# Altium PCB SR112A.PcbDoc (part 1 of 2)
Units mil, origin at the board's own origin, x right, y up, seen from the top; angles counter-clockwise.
Board outline 4000 x 3000 mil, 4 copper layers (Top Layer, Signal Layer 1, Signal Layer 2, Bottom Layer), stack 61.2 mil thick; 97 components, 25 nets, 179 pads, 677 vias.
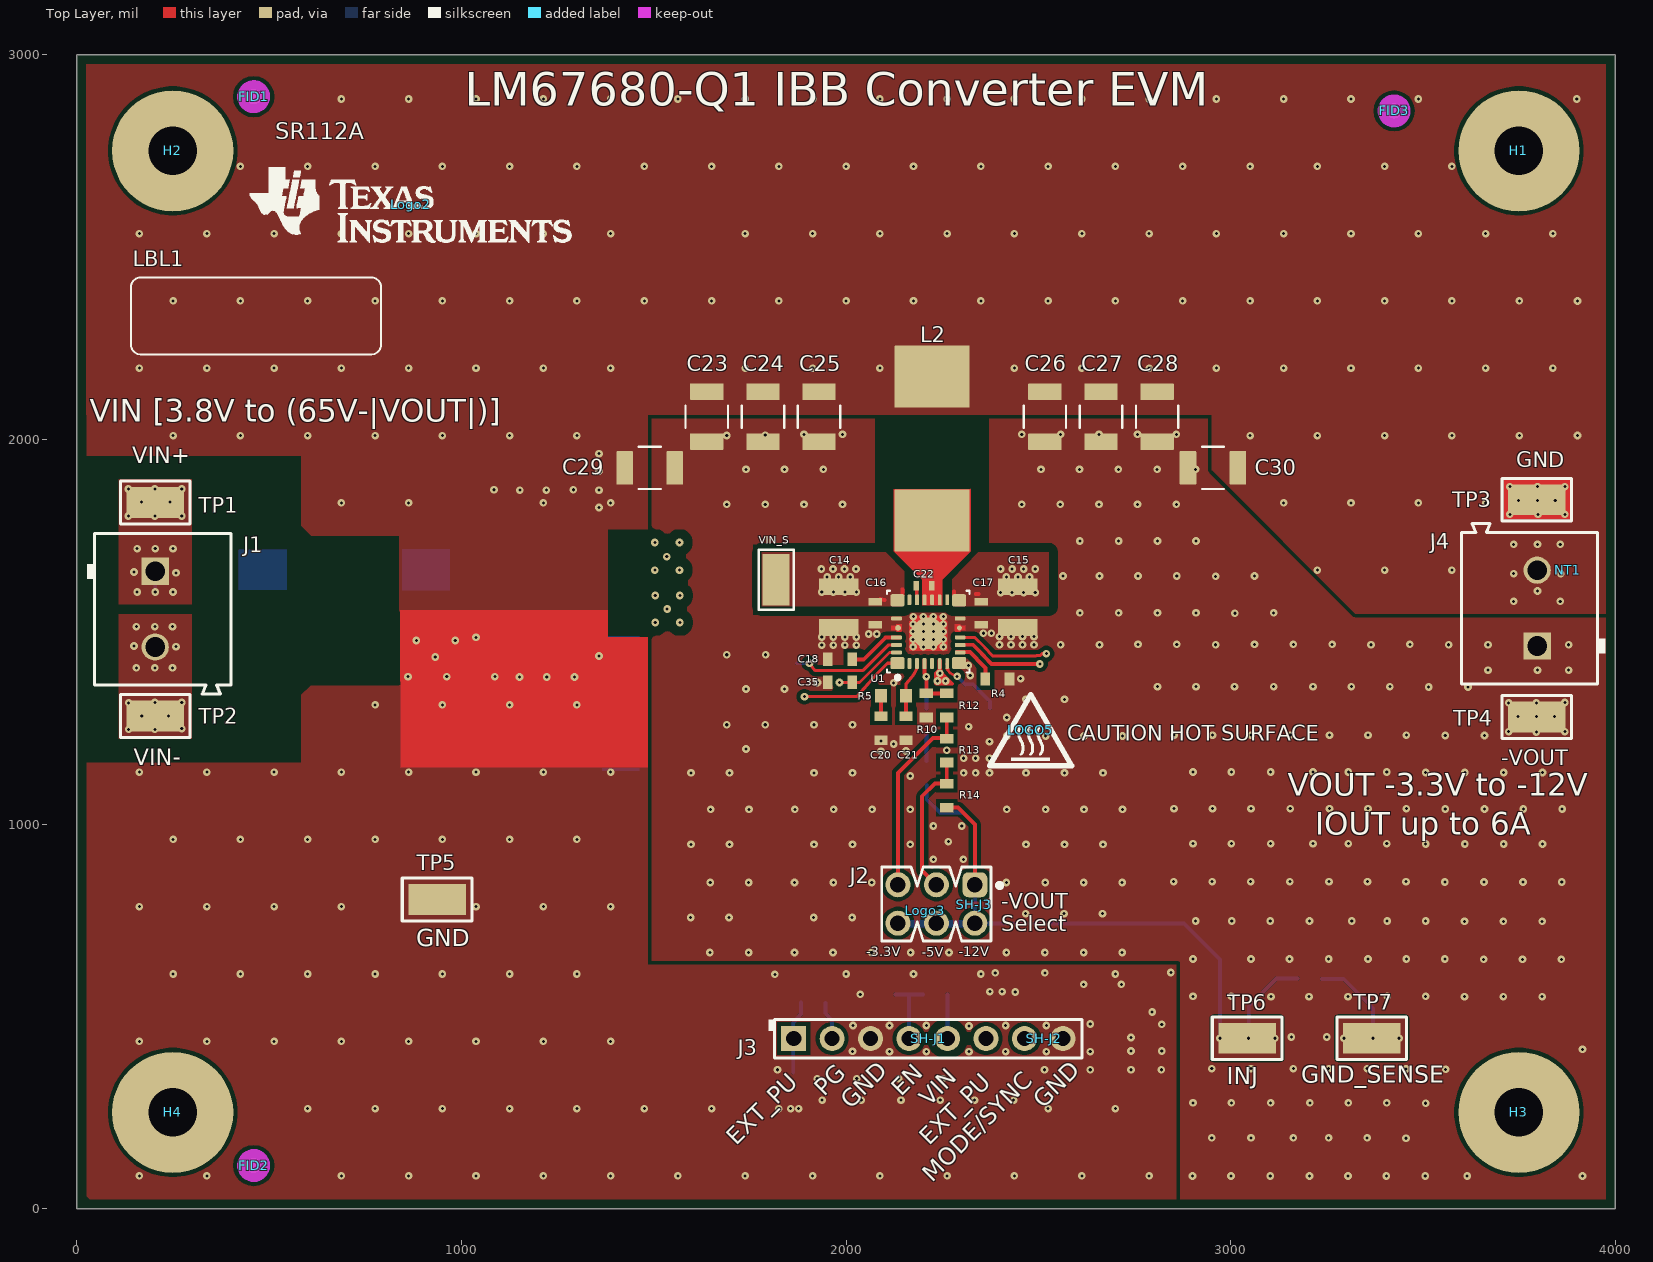
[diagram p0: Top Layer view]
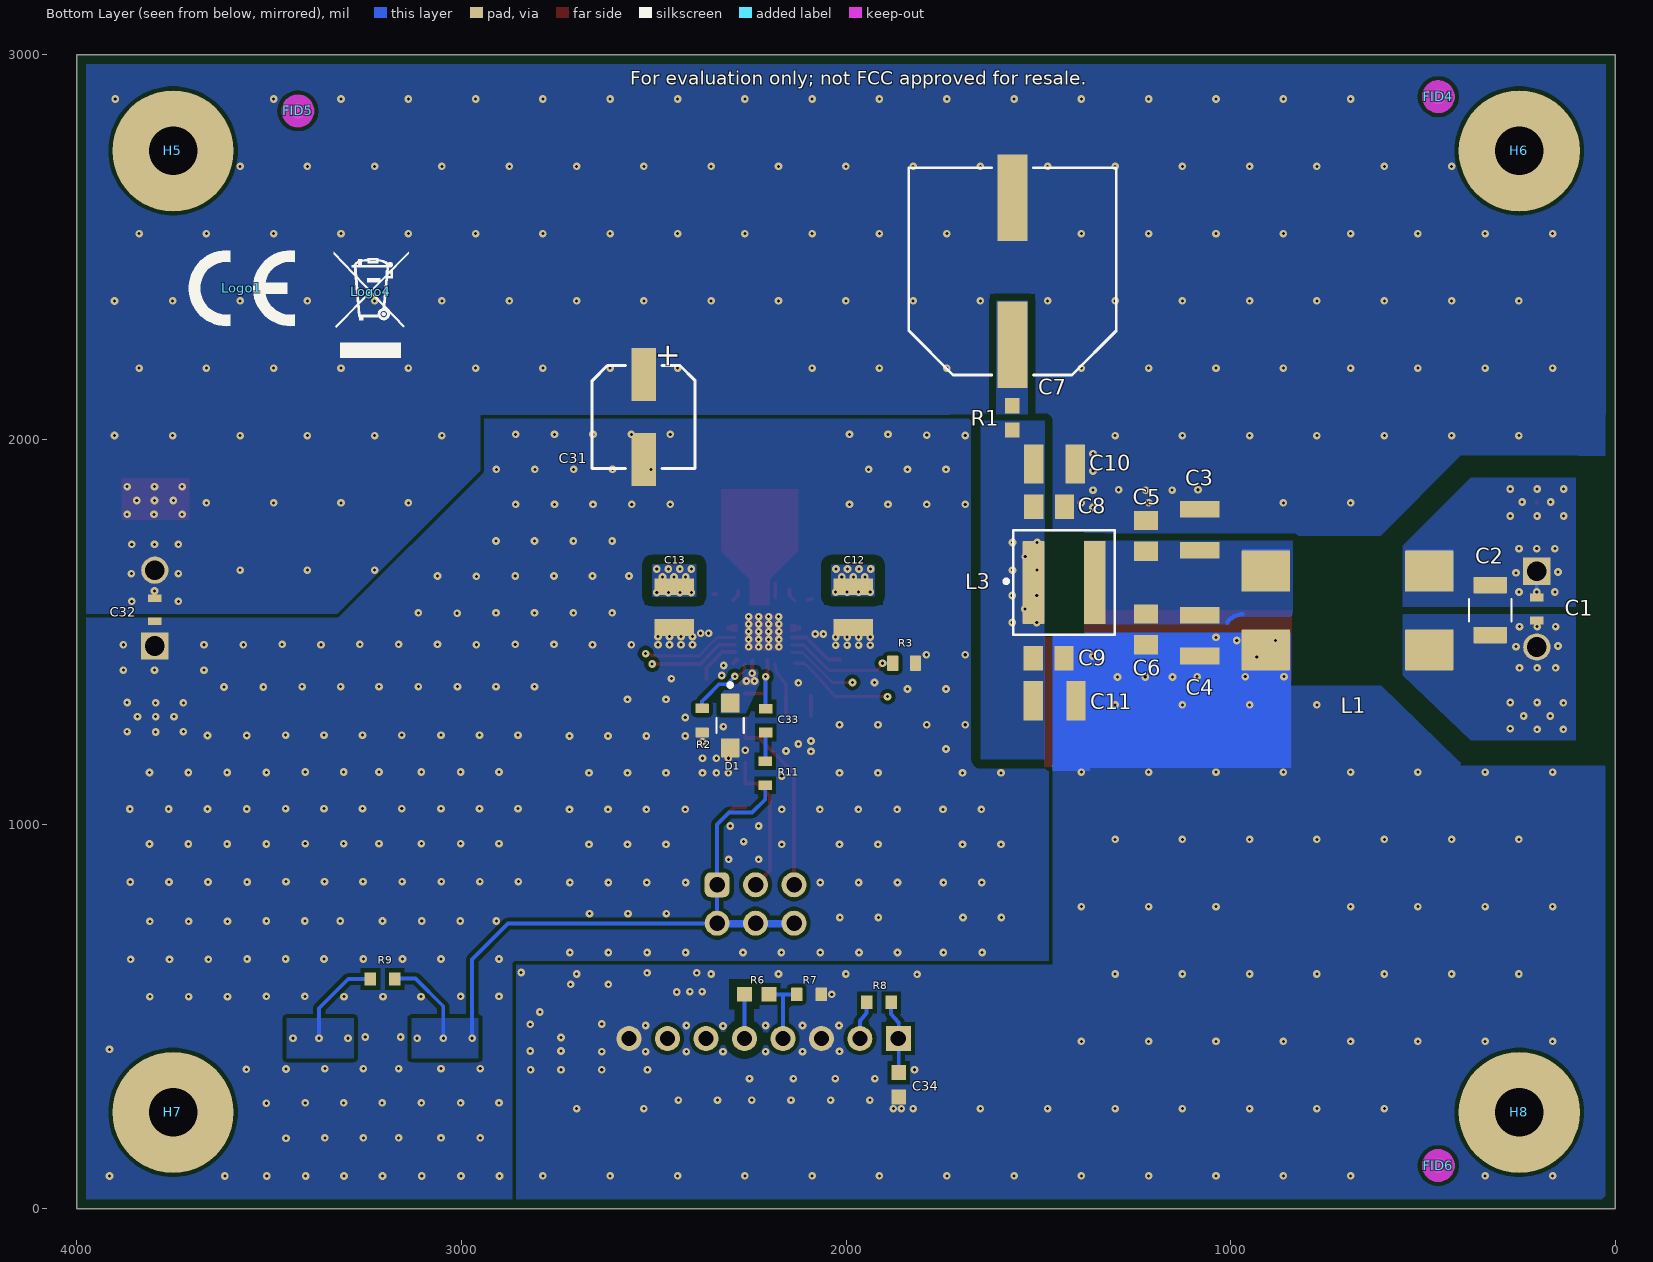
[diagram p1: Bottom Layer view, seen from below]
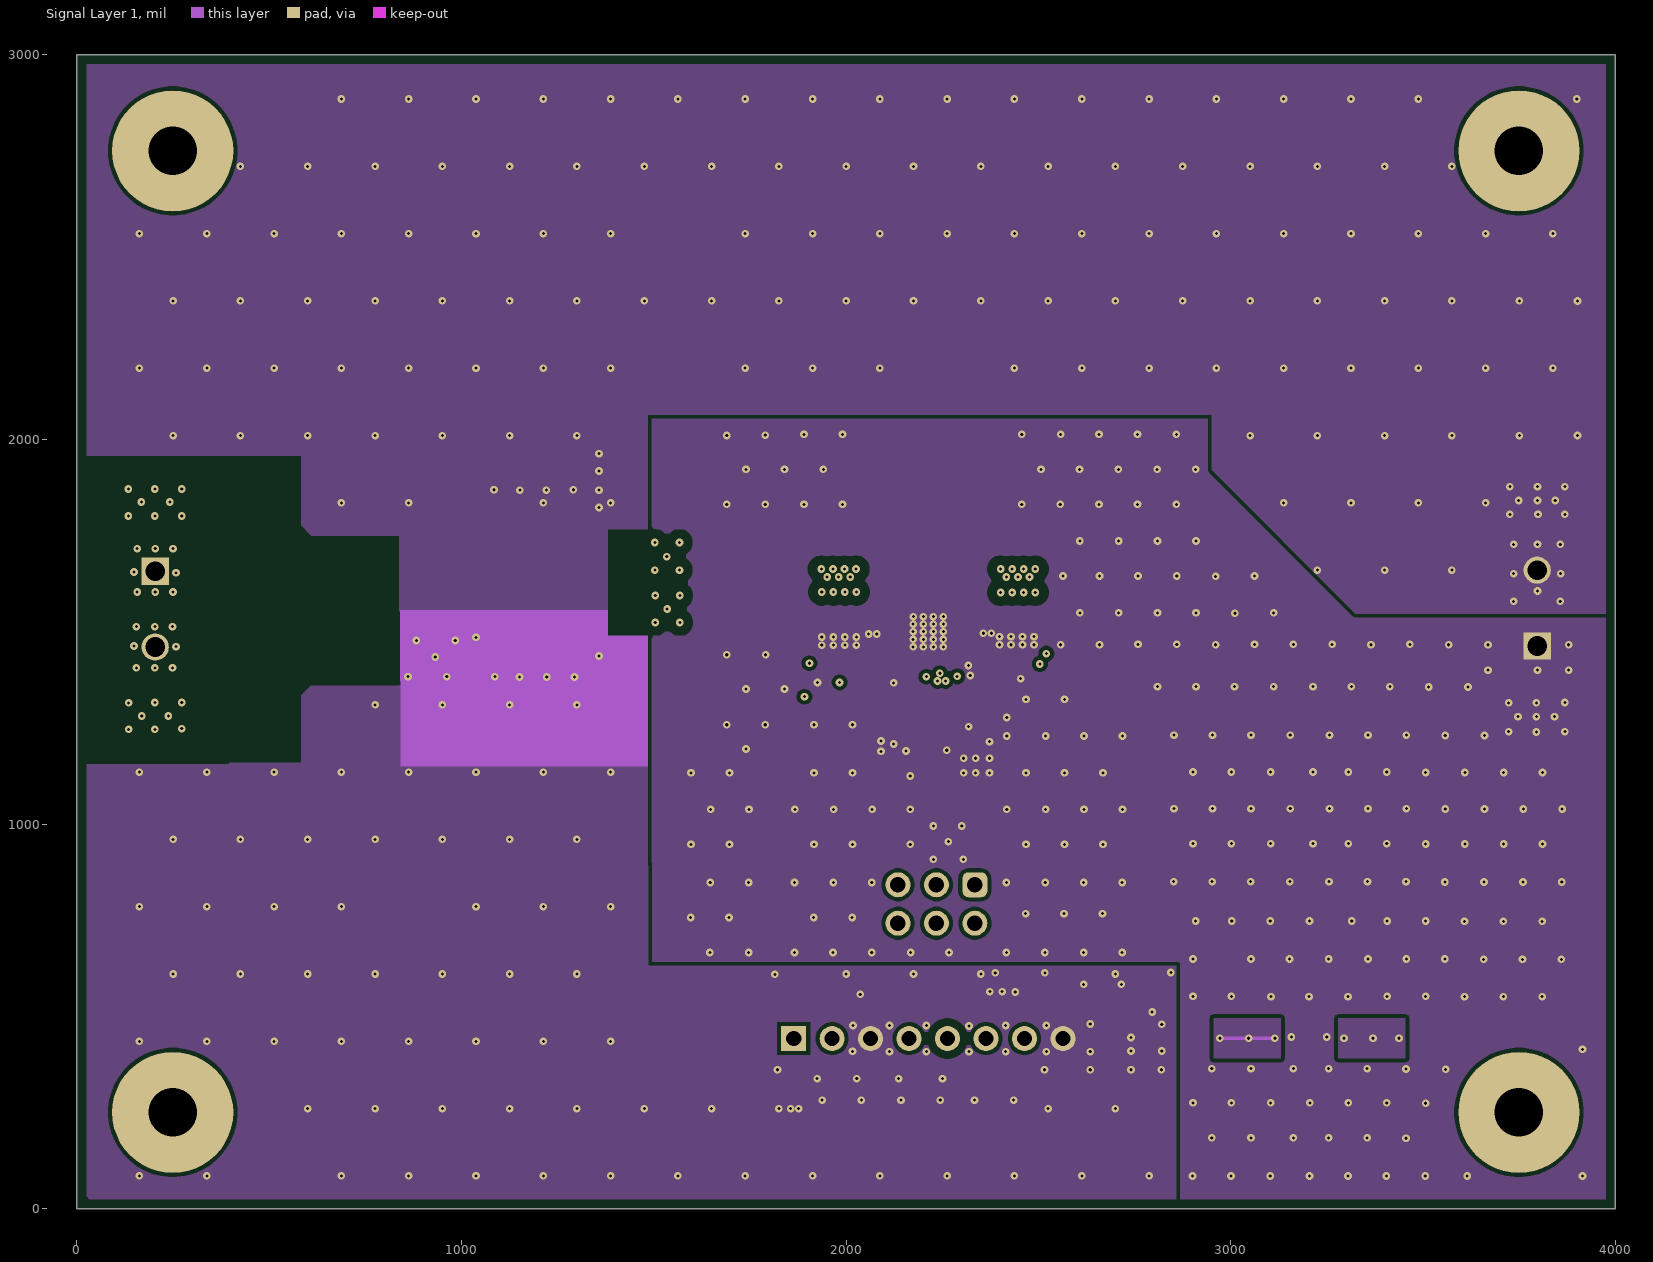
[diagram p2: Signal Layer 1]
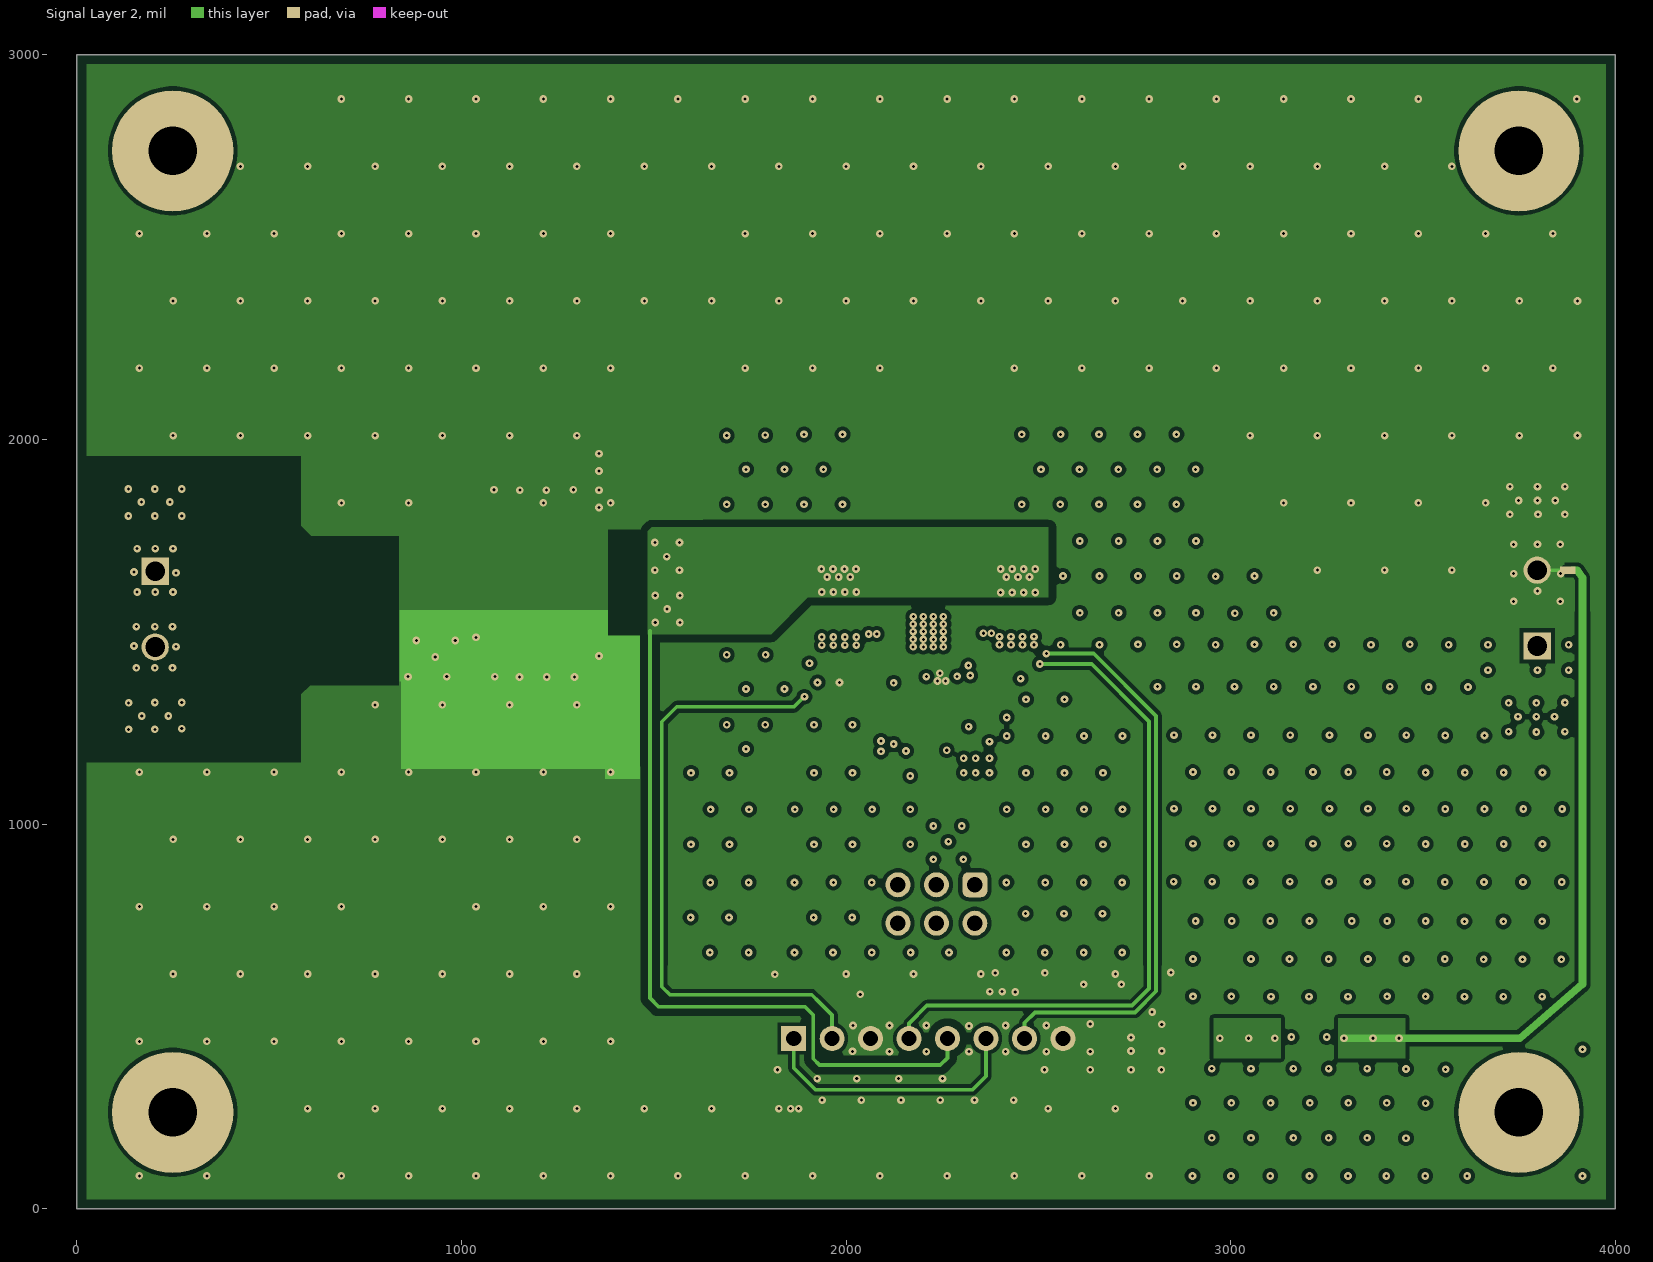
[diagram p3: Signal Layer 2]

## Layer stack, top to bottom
Top Solder: solder mask 0.4, Solder Resist, Dk 3.5
Top Layer: signal copper 2.8
Dielectric1: core 5, FR-4 High Tg, Dk 4.2
Signal Layer 1: signal copper 2.8
Dielectric 2: prepreg 40, FR-4 High Tg, Dk 4.2
Signal Layer 2: signal copper 2.8
Dielectric 3: core 5, FR-4 High Tg, Dk 4.2
Bottom Layer: signal copper 2.8
Bottom Solder: solder mask 0.4, Solder Resist, Dk 3.5

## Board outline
0,0 4000,0 4000,3000 0,3000

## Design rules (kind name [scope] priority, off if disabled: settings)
AcuteAngle [All] p1: minimum=4.50000000000000E+0001 checktracksonly=FALSE
AssemblyTestPointUsage [All] p1: valid=2
BoardOutlineClearance BoardOutlineClearance_MountingHoles [OnCopper and InComponentClass('Mounting Holes')] p1: gap=40 ignorepadtopadclearanceinfootprint=FALSE
BoardOutlineClearance BoardOutlineClearance_Poly [OnCopper and IsPoly] p2: gap=25 ignorepadtopadclearanceinfootprint=FALSE
BoardOutlineClearance [OnCopper and Not InComponentClass('Logo') and not InComponentClass('FiducialMark') and not InRegion(1000,500,4000,800) and not InPoly] p3: gap=75 ignorepadtopadclearanceinfootprint=FALSE
Clearance Clearance_2 [InNet('VIN') vs InNet('-VOUT')] p1: gap=25 ignorepadtopadclearanceinfootprint=TRUE
Clearance "NetC7_1 to GND" [InNet('NetC7_1') vs InNet('GND')] p2: gap=20 ignorepadtopadclearanceinfootprint=FALSE
Clearance "NetC3_1 to GND" [InNet('NetC3_1') vs InNet('GND')] p3: gap=20 ignorepadtopadclearanceinfootprint=FALSE
Clearance "VIN+ to GND" [InNet('VIN+') vs InNet('GND')] p4: gap=20 ignorepadtopadclearanceinfootprint=FALSE
Clearance "VIN- to GND" [InNet('VIN-') vs InNet('GND')] p5: gap=20 ignorepadtopadclearanceinfootprint=FALSE
Clearance "VIN+ to VIN-" [InNet('VIN+') vs InNet('VIN-')] p6: gap=20 ignorepadtopadclearanceinfootprint=FALSE
Clearance "Vin to GND" [InNet('VIN') vs InNet('GND')] p7: gap=20 ignorepadtopadclearanceinfootprint=FALSE
Clearance Clearance_Keepouts [((IsTrack Or IsArc) And Not InPoly) And IsFree and IsKeepOut vs ((IsTrack Or IsArc) And Not InPoly) And IsFree and IsKeepOut] p8: gap=0 ignorepadtopadclearanceinfootprint=FALSE
Clearance Clearance_Poly [InPolygon] p9: gap=10 ignorepadtopadclearanceinfootprint=FALSE
Clearance Clearance_FiducialMark [IsKeepOut and InComponentClass('FiducialMark') vs IsPad and InComponentClass('FiducialMark')] p10: gap=0 ignorepadtopadclearanceinfootprint=FALSE
Clearance [All] p11: gap=7.81 ignorepadtopadclearanceinfootprint=TRUE except(5: Arc-Arc Arc-Track Arc-SMDPad Arc-THPad Arc-Via Arc-Fill Arc-Poly Arc-Region Arc-Text Arc-Hole Track-Track Track-SMDPad Track-THPad Track-Via Track-Fill Track-Poly Track-Region Track-Text Track-Hole)
ComponentClearance ComponentClearance_MountingHoles_FiducialMarks [InComponentClass('Mounting Holes') vs InComponentClass('FiducialMark')] p1: gap=50 collisioncheckmode=3 verticalgap=10 showdistances=FALSE
ComponentClearance ComponentClearance_Shunt [InComponentClass('Header') vs InComponentClass('Shunt')] p2: gap=0 collisioncheckmode=3 verticalgap=0 showdistances=FALSE
ComponentClearance ComponentClearance_Logo [InComponentClass('Logo')] p3: gap=50 collisioncheckmode=3 verticalgap=10 showdistances=FALSE
ComponentClearance ComponentClearance_ScrewToNut [(HasFootprint('NY PMS 440 0025 PH')) vs (HasFootprint('Keystone_1902C'))] p4: gap=5 collisioncheckmode=3 verticalgap=10 showdistances=FALSE
ComponentClearance ComponentClearance_MountingHoles [InComponentClass('Mounting Holes')] p5: gap=50 collisioncheckmode=3 verticalgap=100000 showdistances=FALSE
ComponentClearance ComponentClearance_SmallPassives [HasFootprint('0201*') or HasFootprint('0402*') or HasFootprint('0508') or HasFootprint('0603*') or HasFootprint('0612') or HasFootprint('0805*') or HasFootprint('0815*') or HasFootprint('0830*') or HasFootprint('1206*') or HasFootprint('1210*') or HasFootprint('1808*') or HasFootprint('1812*') or HasFootprint('1825*') or HasFootprint('2010*') or HasFootprint('2220*') or HasFootprint('2225*') or HasFootprint('2512*') or HasFootprint('2728*') or HasFootprint('3518*') vs HasFootprint('0201*') or HasFootprint('0402*') or HasFootprint('0508') or HasFootprint('0603*') or HasFootprint('0612') or HasFootprint('0805*') or HasFootprint('0815*') or HasFootprint('0830*') or HasFootprint('1206*') or HasFootprint('1210*') or HasFootprint('1808*') or HasFootprint('1812*') or HasFootprint('1825*') or HasFootprint('2010*') or HasFootprint('2220*') or HasFootprint('2225*') or HasFootprint('2512*') or HasFootprint('2728*') or HasFootprint('3518*')] p6: gap=14.96 collisioncheckmode=3 verticalgap=10 showdistances=FALSE
ComponentClearance ComponentClearance_THtoSMT [IsThruComponent vs IsSMTComponent] p7: gap=40 collisioncheckmode=3 verticalgap=30 showdistances=FALSE
ComponentClearance ComponentClearance_THtoTH [IsThruComponent vs IsThruComponent] p8: gap=30 collisioncheckmode=3 verticalgap=30 showdistances=FALSE
ComponentClearance [All] p9: gap=10 collisioncheckmode=3 verticalgap=10 showdistances=FALSE
DiffPairsRouting [All] p1: maxlimit=100 minlimit=10 mostfreqgap=10 substack1={BDEA7573-B369-4717-B417-E549E0B5A0E4} toplayer_{bdea7573-b369-4717-b417-e549e0b5a0e4}_minwidth=15 toplayer_{bdea7573-b369-4717-b417-e549e0b5a0e4}_maxwidth=15 toplayer_{bdea7573-b369-4717-b417-e549e0b5a0e4}_prefwidth=15 midlayer1_{bdea7573-b369-4717-b417-e549e0b5a0e4}_minwidth=15 midlayer1_{bdea7573-b369-4717-b417-e549e0b5a0e4}_maxwidth=15 midlayer1_{bdea7573-b369-4717-b417-e549e0b5a0e4}_prefwidth=15 midlayer2_{bdea7573-b369-4717-b417-e549e0b5a0e4}_minwidth=15 midlayer2_{bdea7573-b369-4717-b417-e549e0b5a0e4}_maxwidth=15 midlayer2_{bdea7573-b369-4717-b417-e549e0b5a0e4}_prefwidth=15 bottomlayer_{bdea7573-b369-4717-b417-e549e0b5a0e4}_minwidth=15 bottomlayer_{bdea7573-b369-4717-b417-e549e0b5a0e4}_maxwidth=15 bottomlayer_{bdea7573-b369-4717-b417-e549e0b5a0e4}_prefwidth=15 toplayer_minwidth=15 toplayer_maxwidth=15 toplayer_prefwidth=15 midlayer1_minwidth=15 midlayer1_maxwidth=15 midlayer1_prefwidth=15 midlayer2_minwidth=15 midlayer2_maxwidth=15 midlayer2_prefwidth=15 bottomlayer_minwidth=15 bottomlayer_maxwidth=15 bottomlayer_prefwidth=15 maxuncoupledlength=1000
FabricationTestPointUsage TestPointUsage [All] p1: valid=2 allowmultiple=FALSE
FabricationTestpoint Testpoint [All] p1: side=3 testpointundercomponent=TRUE minsize=40 maxsize=100 preferedsize=60 minholesize=0 maxholesize=40 preferedholesize=32 testpointgrid=1 allowsidetop=TRUE allowsidebottom=TRUE usegrid=TRUE gridtolerance=0.01
FanoutControl Fanout_LCC [IsLCC] p1: bgadir=Out bgaviamode=Centered fanoutstyle=Auto fanoutdirection=Alternating viagrid=1 // Fanout_LCC (Default Rule)
FanoutControl Fanout_BGA [IsBGA] p2: bgadir=Out bgaviamode=Centered fanoutstyle=Auto fanoutdirection=Alternating viagrid=1 // Fanout_BGA (Default Rule)
FanoutControl Fanout_Default [All] p4: bgadir=Out bgaviamode=Centered fanoutstyle=Auto fanoutdirection=Alternating viagrid=1 // Fanout_Default (Default Rule)
FanoutControl Fanout_Small [(CompPinCount < 5)] p5: bgadir=Out bgaviamode=Centered fanoutstyle=Auto fanoutdirection=OutThenIn viagrid=1 // Fanout_Small (Default Rule)
HoleSize [All] p1: absolutevalues=TRUE maxlimit=251 minlimit=7.87 maxpercent=80.000 minpercent=20.000
MinimumAnnularRing MinimumAnnularRing_ThermalPadVias [IsVia and InAnyComponent] p1: minimumring=5.91
MinimumAnnularRing [All] p2: minimumring=5
MinimumSolderMaskSliver MinimumSolderMaskSliver_Logo [InComponentClass('Logo') vs InComponentClass('Logo')] p1: minsoldermaskwidth=3
MinimumSolderMaskSliver [All] p2: minsoldermaskwidth=3
PlaneConnect [All] p1: planeconnectstyle=Direct reliefexpansion=10 reliefentries=4 reliefconductorwidth=10 reliefairgap=10
PolygonConnect [All] p1: connectstyle=Direct reliefconductorwidth=10 reliefentries=4 polygonreliefangle="90 Angle" airgapwidth=10
RoutingVias ThermalPadVias [IsVia and InAnyComponent] p1: holewidth=7.87 width=19.68 viastyle="Through Hole" minholewidth=7.87 minwidth=19.68 maxholewidth=12.99 maxwidth=23.62
RoutingVias [All] p2: holewidth=16 width=34 viastyle="Through Hole" minholewidth=7.87 minwidth=16 maxholewidth=40 maxwidth=65
SilkToBoardRegionClearance [Not ((IsComment or IsDesignator) And (Hide <> 'False')) and not InRegion(1000,500,4000,800)] p1:
SilkToSilkClearance SilkToSilkClearance_Pb-FreeLogo [(HasFootprint('Pb-Free_Overlay_Medium') OR HasFootprint('Pb-Free_Overlay_Small')) vs (HasFootprint('Pb-Free_Overlay_Medium') OR HasFootprint('Pb-Free_Overlay_Small'))] p1: silktosilkclearance=0
SilkToSilkClearance [All] p2: silktosilkclearance=4
SilkToSolderMaskClearance SilkToComponentPadClearance [(IsPad or IsFill or IsRegion) and InAnycomponent] p1: minsilkscreentomaskgap=5 clearancetoexposedcopper=TRUE
SilkToSolderMaskClearance "Silk to Solder Mask Opening" [All] p2: minsilkscreentomaskgap=4 clearancetoexposedcopper=FALSE
SolderMaskExpansion [All] p1: expansion=1.97 istentingtop=FALSE
SupplyNets "Schematic Supply Nets_3" [InNet('GND')] p1: voltage=0.000
SupplyNets "Schematic Supply Nets_2" [InNet('VIN-')] p2: voltage=0.000
SupplyNets "Schematic Supply Nets_1" [InNet('VIN+')] p3: voltage=0.000
SupplyNets "Schematic Supply Nets" [InNet('VIN')] p4: voltage=0.000
Width [All] p1: maxlimit=100 minlimit=6 preferedwidth=10 substack1={BDEA7573-B369-4717-B417-E549E0B5A0E4} checkconnectedcopper=TRUE
15 further rules are at their usual default settings.

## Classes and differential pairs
component class Label: LBL1
component class Header: J2 J3
component class AssemblyNote: ZZ1 ZZ2 ZZ3 ZZ4 ZZ5 ZZ6 ZZ7 ZZ8
component class FiducialMark: FID1 FID2 FID3 FID4 FID5 FID6
component class SR112A_Hardware: FID1 FID2 FID3 FID4 FID5 FID6 H1 H2 H3 H4 H5 H6 H7 H8 LBL1 Logo1 Logo2 Logo3 Logo4 LOGO5 SH-J1 SH-J2 SH-J3 ZZ1 ZZ2 ZZ3 ZZ4 ZZ5 ZZ6 ZZ7 ZZ8
component class Logo: Logo2
component class "Mounting Holes": H1 H2 H3 H4
component class SR112A_Schematic: AGND C1 C2 C3 C4 C5 C6 C7 C8 C9 C10 C11 C12 C13 C14 C15 C16 C17 C18 C20 C21 C22 C23 C24 C25 C26 C27 C28 C29 C30 C31 C32 C33 C34 C35 D1 J1 J2 J3 J4 L1 L2 L3 L5 NT1 q R1 R2 R3 R4 R5 R6 R7 R8 R9 R10 R11 R12 R13 R14 RESET SYNC1 TP1 TP2 TP3 TP4 TP5 TP6 TP7 U1 VIN_DMM1 VIN_S VOUT_DMM1
component class Shunt: SH-J1 SH-J2 SH-J3

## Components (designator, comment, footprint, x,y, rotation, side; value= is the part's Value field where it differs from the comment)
C1 "" 0603S 204,1559 r270 bottom value=0.1uF
C2 "CGA6P1X7R2A106K250AC" FP-CGA6P1X7R2A106K250AC_1210-MFG 325,1556 r270 bottom value=10µF
C3 "GCM32DC72A475KE02L" 1210_220L#1 1080,1765.09 r90 bottom value=4.7uF
C4 "GCM32DC72A475KE02L" 1210_220L#1 1080,1489.91 r270 bottom value=4.7uF
C5 "CGA4J2X7R2A104K125AA" 0805_HV 1220,1749 r90 bottom value=0.1uF
C6 "CGA4J2X7R2A104K125AA" 0805_HV 1220,1506.09 r270 bottom value=0.1uF
C7 "EEV-FK1K680Q" SM_RADIAL_H13 1567,2436.94 r90 bottom value=68uF
C8 "CGA4J2X7R2A104K125AA" 0805_HV 1472,1825 r180 bottom value=0.1uF
C9 "CGA4J2X7R2A104K125AA" 0805_HV 1473,1431 r180 bottom value=0.1uF
C10 "GCM32DC72A475KE02L" 1210_220L#2 1457,1936 r180 bottom value=4.7uF
C11 "GCM32DC72A475KE02L" 1210_220L#3 1458,1320 r180 bottom value=4.7uF
C12 "GCM32DC72A475KE02L" 1210_220L#1 1981,1564 r270 bottom value=4.7uF
C13 "GCM32DC72A475KE02L" 1210_220L#1 2447,1564 r270 bottom value=4.7uF
C14 "GCM32DC72A475KE02L" 1210_220L#1 1981,1564 r270 top value=4.7uF
C15 "GCM32DC72A475KE02L" 1210_220L#1 2447,1564 r270 top value=4.7uF
C16 "CINHF1" 0603S 2076,1548 r270 top value=0.1uF
C17 "CINHF2" 0603S 2352,1548 r270 top value=0.1uF
C18 "CGA3E3X5R1H105M080AB" 0603#1 1985,1428 r180 top value=1uF
C20 "CGA3E2C0G1H103J080AA" 0603#2 2091,1248 r270 top value=0.01uF
C21 "DNP" 0603#3 2156,1251 r90 top value=10pF
C22 "CGA2B3X7R1H104K050BB" 0402 2204,1619 r0 top value=0.1uF
C23 "CGA6P3X7R1E226M250AB" FP-CGA6P3X7R1E226M250AB_1210-MFG 1638,2059 r90 top value=22µF
C24 "CGA6P3X7R1E226M250AB" FP-CGA6P3X7R1E226M250AB_1210-MFG 1784,2059 r90 top value=22µF
C25 "CGA6P3X7R1E226M250AB" FP-CGA6P3X7R1E226M250AB_1210-MFG 1930,2059 r90 top value=22µF
C26 "CGA6P3X7R1E226M250AB" FP-CGA6P3X7R1E226M250AB_1210-MFG 2517,2059 r90 top value=22µF
C27 "CGA6P3X7R1E226M250AB" FP-CGA6P3X7R1E226M250AB_1210-MFG 2663,2059 r90 top value=22µF
C28 "CGA6P3X7R1E226M250AB" FP-CGA6P3X7R1E226M250AB_1210-MFG 2809,2059 r90 top value=22µF
C29 "DNP" FP-CGA6P3X7R1E226M250AB_1210-MFG 1490,1926 r180 top value=22µF
C30 "DNP" FP-CGA6P3X7R1E226M250AB_1210-MFG 2954,1926 r0 top value=22µF
C31 "DNP" WCAP-PSLP_630x580 2526,2058 r270 bottom value=82uF
C32 "CINHF1" 0603S 3797,1557 r270 bottom value=0.1uF
C33 "DNP" 0603#4 2209,1270 r270 bottom value=10pF
C34 "GCM188R71C105MA64D" 0603#5 1863,322 r270 bottom value=1uF
C35 "CGA3E3X5R1H105M080AB" 0603#1 1985,1368 r180 top value=1uF
D1 "NRVB120VLSFT1G" FP-NRVB120VLSFT1G_SOD-123-MFG 2301,1256 r270 bottom
FID1 "Fiducial" Fiducial10-20 460,2891 r0 top
FID2 "Fiducial" Fiducial10-20 460,112 r0 top
FID3 "Fiducial" Fiducial10-20 3425,2854 r0 top
FID4 "Fiducial" Fiducial10-20 460,2891 r180 bottom
FID5 "Fiducial" Fiducial10-20 3425,2854 r180 bottom
FID6 "Fiducial" Fiducial10-20 460,112 r180 bottom
H1 "NY PMS 440 0025 PH" "NY PMS 440 0025 PH" 3749.51,2750.18 r90 top
H2 "NY PMS 440 0025 PH" "NY PMS 440 0025 PH" 249.51,2750.18 r90 top
H3 "NY PMS 440 0025 PH" "NY PMS 440 0025 PH" 3749.51,250.18 r90 top
H4 "NY PMS 440 0025 PH" "NY PMS 440 0025 PH" 249.51,250.18 r90 top
H5 "1902C" Keystone_1902C 3750,2750 r90 bottom
H6 "1902C" Keystone_1902C 250,2750 r90 bottom
H7 "1902C" Keystone_1902C 3750,250 r90 bottom
H8 "1902C" Keystone_1902C 250,250 r90 bottom
J1 "691 101 710 002" Wurth_691101710002 204,1558.43 r270 top
J2 "" TE_5-146254-3 2235,792 r180 top
J3 "5-146278-8" TE_5-146278-8 2214,442 r0 top
J4 "691 101 710 002" Wurth_691101710002 3797,1561.43 r90 top
L1 "ACM12V-701-2PL-TL00" TDK_ACM12V 696,1555 r0 bottom
L2 "VCHA105D-6R8MS6" VCHA105D 2224,1976 r90 top value=6.8uH
L3 "" FP-XGL6060-332MEC_SMT_6MM51_6MM71-MFG 1433,1628 r180 bottom value=3.3uH
LBL1 "THT-14-423-10" Label_650x200 466,2321 r0 top
Logo1 "CE Mark" CE_Mark_5mm 3571,2393 r180 bottom
Logo2 "Texas Instruments" TI_Stacked_Overlay_Small 868,2610 r0 top
Logo3 "FCC disclaimer" FCC_disclaimer 2206,774 r0 top
Logo4 "WEEE logo" WEEE_Minimum 3236,2384 r180 bottom
LOGO5 "CAUTION HOT SURFACE" IEC_HotSurface_Small 2480,1244 r0 top
NT1 "Net-Tie" Net-Tie_10mil 3877,1660 r0 top net-tie
R1 "ERJ-3RQFR51V" 0603#5 1568,2056 r270 bottom value=0.51
R2 "CRCW060349K9FKEA" FP-CRCW060349K9FKEA_0603-MFG#1 2374,1270 r90 bottom
R3 "CRCW060349K9FKEA" FP-CRCW060349K9FKEA_0603-MFG#2 1849,1418 r0 bottom
R4 "CRCW060340K2FKEA" 0603#6 2394,1377 r180 top value=40.2k
R5 "CRCW060313K3FKEA" 0603#7 2124.5,1333 r0 top value=13.3k
R6 "CRCW0603226KFKEA" 0603#5 2232,557 r0 bottom value=226k
R7 "CRCW060349K9FKEA" FP-CRCW060349K9FKEA_0603-MFG#3 2096,557 r0 bottom
R8 "CRCW0603100KFKEA" 0603#8 1913,536 r0 bottom value=100k
R9 "CRCW060349R9FKEA" 0603#9 3205,597 r0 bottom value=49.9
R10 "CRCW060310K0FKEA" 0603#10 2209,1308 r90 top value=10.0k
R11 "RMCF0603ZT0R00" 0603#11 2210,1129 r270 bottom value=0
R12 "CRCW060331K6FKEA" 0603#12 2262,1307 r90 top value=31.6k
R13 "CRCW060321K0FKEA" 0603#4 2262,1190 r90 top value=21.0k
R14 "CRCW060386K6FKEA" 0603#13 2262,1073.5 r270 top value=86.6k
SH-J1 "SNT-100-BK-G" SNT-100-BK-G 2215,442 r0 top value=1x2
SH-J2 "SNT-100-BK-G" SNT-100-BK-G 2515,442 r0 top value=1x2
SH-J3 "SNT-100-BK-G" SNT-100-BK-G 2334,790 r90 top value=1x2
TP1 "VIN+" Keystone_5019#1 204,1836 r0 top
TP2 "VIN-" Keystone_5019#1 204,1281 r0 top
TP3 "GND" Keystone_5019#2 3796,1843 r0 top
TP4 "-VOUT" Keystone_5019#2 3796,1278 r0 top
TP5 "GND" Keystone_5019#2 937,804 r0 top
TP6 "INJ" Keystone_5019#2 3043,443 r0 top
TP7 "GND_SENSE" Keystone_5019#2 3367,443 r0 top
U1 "LM67680RZYRQ1" RZY0026A-MFG 2214,1499.94 r90 top
VIN_S "5015" Testpoint_Keystone_Miniature 1818,1635 r90 top
ZZ1 "These assemblies are ESD sensitive, ESD precautions shall be observed." AssemblyNote 185,4304 r0 top
ZZ2 "These assemblies must be clean and free from flux and all contaminants. Use of no clean flux is not acceptable." AssemblyNote 185,4231 r0 top
ZZ3 "These assemblies must comply with workmanship standards IPC-A-610 Class 2, unless otherwise specified." AssemblyNote 185,4152 r0 top
ZZ4 "Assemble L1 with dot/bar/WE logo closer to the L1 marking" AssemblyNote 185.41,4071 r0 top
ZZ5 "Install Shunt Jumper SH-J1 onto J3 pins 4-5 (EN-VIN)" AssemblyNote 186,3996 r0 top
ZZ6 "Install Shunt Jumper SH-J2 onto J3 pins 7-8 (MODE/SYNC-GND)" AssemblyNote 186,3917 r0 top
ZZ7 "Install Shunt Jumper SH-J3 onto J2 pins 5-6 (sets output voltage to -12V)" AssemblyNote 186,3841 r0 top
ZZ8 "This Assembly Note is for PCB labels only" AssemblyNoteLabel 186,3768 r0 top

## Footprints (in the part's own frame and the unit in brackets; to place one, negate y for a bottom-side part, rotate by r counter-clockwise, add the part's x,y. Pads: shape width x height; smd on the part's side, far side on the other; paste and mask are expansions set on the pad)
0402 [mil] "0402 from SM-752 data"
  rect 15x25 smd: 1(-21.5,0) 2(19,0)
  body extent -22,-12 22,12, height 24
0603#1 [mil] "0603 from SM-752 data"
  rect 25x35 smd: 1(-31.5,0) 2(32,0)
  body extent -34,-19 34,19, height 39
0603#2 [mil] "0603 from SM-752 data"
  rect 25x35 smd: 1(-32,0) 2(30.5,0)
  body extent -34,-19 34,19, height 39
0603#3 [mil] "0603 from SM-752 data"
  rect 25x35 smd: 1(-33.5,0) 2(29,0)
  body extent -34,-19 34,19, height 39
0603#4 [mil] "0603 from SM-752 data"
  rect 25x35 smd: 1(-30,0) 2(32,0)
  body extent -34,-19 34,19, height 39
0603#5 [mil] "0603 from SM-752 data"
  rect 39.37x37.4 smd: 1(-31.5,0) 2(31.5,0)
  body extent -34,-19 34,19, height 39
0603#6 [mil] "0603 from SM-752 data"
  rect 25x35 smd paste+0 mask+1.97: 1(-31,0)
  rect 25x35 smd: 2(31.5,0)
  body extent -34,-19 34,19, height 39
0603#7 [mil] "0603 from SM-752 data"
  rect 30x35 smd: 1(-33.5,0) 2(31.5,0)
  body extent -34,-19 34,19, height 39
0603#8 [mil] "0603 from SM-752 data"
  rect 30x35 smd: 1(-30.5,0) 2(32.5,0)
  body extent -34,-19 34,19, height 39
0603#9 [mil] "0603 from SM-752 data"
  rect 30x35 smd: 1(-31.5,0) 2(31.5,0)
  body extent -34,-19 34,19, height 39
0603#10 [mil] "0603 from SM-752 data"
  rect 25x35 smd: 1(-31,0) 2(31.5,0)
  body extent -34,-19 34,19, height 39
0603#11 [mil] "0603 from SM-752 data"
  rect 25x35 smd: 1(-34,0) 2(28,0)
  body extent -34,-19 34,19, height 39
0603#12 [mil] "0603 from SM-752 data"
  rect 25x35 smd: 1(-30,0) 2(32.5,0)
  body extent -34,-19 34,19, height 39
0603#13 [mil] "0603 from SM-752 data"
  rect 25x35 smd: 1(-31.5,0) 2(31.5,0)
  body extent -34,-19 34,19, height 39
0603S [mil]
  rect 20x35 smd: 1(-30,0) 2(30,0)
  body extent -34,-19 34,19, height 39
0805_HV [mil] "0805 with 30mil clearance between pads"
  rect 50x63 smd: 1(-40,0) 2(40,0)
  body extent -43,-29 43,29, height 57
1210_220L#1 [mm] "1210"
  rect 1.1x2.6 smd: 1(-1.35,0) 2(1.35,0)
  body extent -1.7,-1.35 1.7,1.35, height 2.2
1210_220L#2 [mm] "1210"
  rect 1.27x2.6 smd: 1(-1.397,0) 2(1.35,0)
  body extent -1.7,-1.35 1.7,1.35, height 2.2
1210_220L#3 [mm] "1210"
  rect 1.27x2.6 smd: 1(-1.397,0) 2(1.422,0)
  body extent -1.7,-1.35 1.7,1.35, height 2.2
AssemblyNote [mil] "Assembly Note"
AssemblyNoteLabel [mil] "Assembly Note for PCB Labels"
CE_Mark_5mm [mil] "Minimum text height for CE Mark"
  silkscreen extent -138,-98 138,98
FCC_disclaimer [mil]
Fiducial10-20 [mm]
  round 1 smd mask+0.5: 1(0,0)
  Top Layer keep-out circle w1.178: c0,0 r0.5
FP-CGA6P1X7R2A106K250AC_1210-MFG [mm] "Recommended Land Pattern"
  rrect9% 1.1x2.2 smd paste+0 mask+0: 1(-1.65,0) 2(1.65,0)
  silkscreen extent -0.72,-1.4 0.72,1.4, body extent -1.6,-1.25 1.6,1.25, height 2.81
FP-CGA6P3X7R1E226M250AB_1210-MFG [mm]
  rrect9% 1.1x2.2 smd paste+0 mask+0: 1(-1.65,0) 2(1.65,0)
  silkscreen extent -0.72,-1.4 0.72,1.4, body extent -2.3,-1.5 2.3,1.5, height 0.25
FP-CRCW060349K9FKEA_0603-MFG#1 [mil]
  rrect13% 25x35 smd paste+0 mask+0: 1(-32,0) 2(30.5,0)
  body extent -31,-17 31,17, height 22
FP-CRCW060349K9FKEA_0603-MFG#2 [mil]
  rrect13% 29.53x39.37 smd paste+0 mask+0: 1(-29.53,0) 2(29.53,0)
  body extent -31,-17 31,17, height 22
FP-CRCW060349K9FKEA_0603-MFG#3 [mil]
  rrect13% 30x35 smd paste+0 mask+0: 1(-32,0) 2(32,0)
  body extent -31,-17 31,17, height 22
FP-NRVB120VLSFT1G_SOD-123-MFG [mm] "Recommended Land Pattern"
  rrect8% 1.25x1.22 smd paste+0 mask+0: 1(-1.475,0) 2(1.475,0)
  silkscreen extent -2.8,-0.9 0.48,0.9, body extent -1.8,-0.82 1.8,0.82, height 0.98
FP-XGL6060-332MEC_SMT_6MM51_6MM71-MFG [mm]
  rrect7% 1.43x5.5 smd paste+0 mask+0: 1(-2.02,0) 2(2.02,0)
  silkscreen extent -3.95,-3.45 3.35,3.45, body extent -3.25,-3.35 3.25,3.35, height 6.1
IEC_HotSurface_Small [mil]
  silkscreen extent -107,-93 107,92
Keystone_1902C [mil] "Hex Standoff, 4-40 threaded, nylon"
  round 1 on Mech4: 0(0,0)
  body extent -145,-126 146,126, height 501
Keystone_5019#1 [mil] "Test Point, Miniature, SMT"
  rect 150x80 smd: 1(0,0)
  silkscreen extent -91,-56 91,56, body extent -75,-40 75,40, height 90
Keystone_5019#2 [mil] "Test Point, Miniature, SMT"
  rect 149.61x79.92 smd: 1(0,0)
  silkscreen extent -91,-56 91,56, body extent -75,-40 75,40, height 90
Label_650x200 [mil] "Thermal Transfer Label"
  round 1 on Mech13: 0(0,0)
  silkscreen extent -325,-100 325,100, body extent -325,-100 325,100, height 1
Net-Tie_10mil [mil] "10mil net tie, no solder mask opening, no solder paste"
  rect 20x20 on Mid2 paste-5 mask-5: 1(-10,0) 2(10,0)
  Signal Layer 2 region: -6,5 6,5 6,-5 -6,-5
"NY PMS 440 0025 PH" [mm] "4-40 nylon screw and mounting hole"
  round 8 hole 3.2: 1(0,0)
  body extent -3.3,-3.3 3.3,3.3, height 2.69
RZY0026A-MFG [mm] "Recommended Land Pattern"
  rrect25% 0.8x0.925 smd paste-1000 mask-1000: 1(-2.075,2.037) 8(-2.075,-2.037) 14(2.075,-2.037) 21(2.075,2.037)
  rrect40% 0.7x0.25 smd paste+0 mask+0: 2(-2.1,1.25) 3(-2.1,0.75) 4(-2.1,0.25) 5(-2.1,-0.25) 6(-2.1,-0.75) 7(-2.1,-1.25) 15(2.1,-1.25) 16(2.1,-0.75) 17(2.1,-0.25) 18(2.1,0.25) 19(2.1,0.75) 20(2.1,1.25)
  rrect40% 0.25x0.7 smd paste+0 mask+0: 9(-1.375,-2.1) 10(-0.875,-2.1) 11(-0.375,-2.1) 13(0.875,-2.1) 22(0.875,2.1) 24(-0.375,2.1) 25(-0.875,2.1) 26(-1.375,2.1)
  round 0.32 smd paste+0 mask+0: 12(0.25,-2.057)
  round 0.377 smd paste+0 mask+0: 23(0.25,2)
  round 2.07 smd paste-1000 mask+0: 27(-0.1,0)
  Top Layer region: 0.45,-1.75 0.469,-1.754 0.485,-1.765 0.496,-1.781 0.5,-1.8 0.5,-1.8 0.5,-2.065 0.493,-2.09 0.475,-2.108 0.45,-2.115 0.45,-2.115 0.431,-2.119 0.415,-2.13 0.404,-2.146 0.4,-2.165 0.4,-2.165 0.4,-2.4 0.393,-2.425 0.375,-2.443 0.35,-2.45 0.35,-2.45 0.15,-2.45 0.131,-2.446 0.115,-2.435 0.104,-2.419 0.1,-2.4 0.1,-2.4 0.1,-2.165 0.096,-2.146 0.085,-2.13 0.069,-2.119 0.05,-2.115 0.05,-2.115 0.025,-2.108 0.007,-2.09 0,-2.065 0,-2.065 0,-1.8 0.004,-1.781 0.015,-1.765 0.031,-1.754 0.05,-1.75 0.05,-1.75
  Top Layer region: 0.05,1.75 0.031,1.754 0.015,1.765 0.004,1.781 0,1.8 0,1.8 0,2.065 0.007,2.09 0.025,2.108 0.05,2.115 0.05,2.115 0.069,2.119 0.085,2.13 0.096,2.146 0.1,2.165 0.1,2.165 0.1,2.4 0.107,2.425 0.125,2.443 0.15,2.45 0.15,2.45 0.35,2.45 0.369,2.446 0.385,2.435 0.396,2.419 0.4,2.4 0.4,2.4 0.4,2.165 0.404,2.146 0.415,2.13 0.431,2.119 0.45,2.115 0.45,2.115 0.469,2.111 0.485,2.1 0.496,2.084 0.5,2.065 0.5,2.065 0.5,1.8 0.496,1.781 0.485,1.765 0.469,1.754 0.45,1.75 0.45,1.75
  Top Layer region: -1.25,1.2 -1.243,1.225 -1.225,1.243 -1.2,1.25 -1.2,1.25 0.657,1.25 0.678,1.245 0.695,1.232 0.695,1.232 1.038,0.822 1.047,0.807 1.05,0.79 1.05,0.79 1.05,-0.79 1.047,-0.807 1.038,-0.822 1.038,-0.822 0.695,-1.232 0.678,-1.245 0.657,-1.25 0.657,-1.25 -1.2,-1.25 -1.225,-1.243 -1.243,-1.225 -1.25,-1.2 -1.25,-1.2
  silkscreen extent -3.15,-2.73 2.7,2.73, body extent -2.25,-2.25 2.25,2.25, height 0.7
SM_RADIAL_H13 [mm] "12.5 x 13.5mm:  Panasonic H13"
  rect 5.7x2 smd: 1(-4.85,0) 2(4.85,0)
  silkscreen extent -6.85,-6.85 6.85,6.85, body extent -6.85,-6.85 6.85,6.85, height 14
SNT-100-BK-G [mil] "Samtec STEP model"
  round 1 on Mech3: 0(0,0)
  body extent -100,-50 100,50, height 344
TDK_ACM12V [mm] "SMD, 4-Leads, Body 12x11mm, Pitch 5.2mm"
  rrect4% 3.2x2.7 smd: 1(-5.4,2.6) 2(-5.4,-2.6) 3(5.4,-2.6) 4(5.4,2.6)
  body extent -6,-5.5 6,5.5, height 5.55
TE_5-146254-3 [mm] "TE 100mil, 3x2"
  rrect50% 1.65x1.65 hole 1.016: 1(-2.54,-1.27)
  round 1.65 hole 1.016: 2(-2.54,1.27) 3(0,-1.27) 4(0,1.27) 5(2.54,-1.27) 6(2.54,1.27)
  silkscreen extent -4.33,-2.44 3.61,2.44, body extent -3.61,-2.44 3.61,2.44, height 8.14
TE_5-146278-8 [mm] "TE CONNECTIVITY"
  rect 1.65x1.65 hole 1: 1(-8.89,0)
  round 1.65 hole 1: 2(-6.35,0) 3(-3.81,0) 4(-1.27,0) 5(1.27,0) 6(3.81,0) 7(6.35,0) 8(8.89,0)
  silkscreen extent -10.54,-1.27 10.16,1.27, body extent -10.03,-1.17 10.03,1.17, height 8.13
Testpoint_Keystone_Miniature [mil] "Miniature SMT test point"
  rect 135x70 smd: 1(0,0)
  silkscreen extent -78,-46 78,45, body extent -52,-20 52,20, height 61
TI_Stacked_Overlay_Small [mil]
  silkscreen extent -418,-98 418,98
VCHA105D [mm] "SMD, 2-Leads, Body 10.85x10mm"
  rrect2% 4.1x4.95 smd: 1(-4.75,0) 2(4.75,0)
  body extent -5.6,-5.15 5.6,5.15, height 5.4
WCAP-PSLP_630x580 [mm] "SMD, 2-Leads, Dia 6.3mm"
  rect 3.5x1.6 smd: 1(-2.8,0) 2(2.8,0)
  silkscreen extent -3.4,-3.4 3.4,3.4, body extent -3.4,-3.4 3.4,3.4, height 5.81
WEEE_Minimum [mil] "WEEElie bin"
  silkscreen extent -95,-172 99,104
Wurth_691101710002 [mm] "Terminal Block, 5 mm, 2x1, TH"
  rect 1.8x1.8 hole 1.3: 1(-2.5,0)
  round 1.8 hole 1.3: 2(2.5,0)
  silkscreen extent -5,-4.5 5.6,5, body extent -5.6,-4 5.6,5, height 12.5

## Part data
C1 C16 C17 C32: library part CMP-0064935-4, "CAP, CERM, 0.1 uF, 100 V,+/- 10%, X7R, AEC-Q200 Grade 1, 0603", Cap_Case=0603, Manufacturer=MuRata, PartNumber=GCJ188R72A104KA01D, Supplier Part Number 1=490-13420-1-ND, TempCo=X7R, Tolerance_%=10%, Value1=Unknown, Value2=100V, ValueDisplayed=0.1uF
C2: library part CMP-0125410-1, "10 µF ±10% 100V Ceramic Capacitor X7R 1210 (3225 Metric)", Digikey Part Number=445-CGA6P1X7R2A106K250ACCT-ND, Manufacturer=TDK, Mouser Part Number=810-CGA6P1X7R2A106K2, Operating Temperature Range="-55°C to +125°C", TempCo=15%, Temperature Characteristic=X7R, Tolerance_%=10%, ValueDisplayed=10uF
C3 C4 C10 C11 C12 C13 C14 C15: library part CMP-0082268-1, "CAP, CERM, 4.7 µF, 100 V,+/- 10%, X7S, AEC-Q200 Grade 1, 1210", Cap_Case=1210, Manufacturer=MuRata, Supplier Part Number 1=490-14484-1-ND, TempCo=X7S, Tolerance_%=10%, Value1="0.001 ohm", Value2=100V, ValueDisplayed=4.7µF
C5 C6 C8 C9: library part CMP-0007969-2, "CAP, CERM, 0.1 uF, 100 V, +/- 10%, X7R, AEC-Q200 Grade 1, 0805", Cap_Case=0805, Manufacturer=TDK, Supplier Part Number 1=445-5827-1-ND, TempCo=X7R, Tolerance_%=10%, Value1="0.020726 ohm", Value2=100V, ValueDisplayed=0.1uF
C7: library part CMP-0011220-2, "CAP, AL, 68 uF, 80 V, +/- 20%, 0.32 ohm, AEC-Q200 Grade 2, SMD", Cap_Case=H13, Manufacturer=Panasonic, Supplier Part Number 1=PCE3528CT-ND, Tolerance_%=20%, Value1="0.32 ohm", Value2=80V, ValueDisplayed=68uF
C18 C35: library part CMP-0083707-1, "CAP, CERM, 1 µF, 50 V,+/- 20%, X5R, AEC-Q200 Grade 3, 0603", Cap_Case=0603, Manufacturer=TDK, Supplier Part Number 1=445-12510-1-ND, TempCo=X5R, Tolerance_%=20%, Value2=50V, ValueDisplayed=1µF
C20: library part CMP-0007070-4, "CAP, CERM, 0.01 uF, 50 V, +/- 5%, C0G/NP0, AEC-Q200 Grade 1, 0603", Cap_Case=0603, Manufacturer=TDK, Supplier Part Number 1=445-6916-1-ND, TempCo=C0G/NP0, Tolerance_%=5%, Value1=Unknown, Value2=50V, ValueDisplayed=10nF
C21 C33: library part CMP-0007170-4, "CAP, CERM, 10 pF, 50 V, +/- 5%, C0G/NP0, 0603", Cap_Case=0603, Manufacturer=MuRata, PartNumber=GRM1885C1H100JA01D, Supplier Part Number 1=490-1403-1-ND, TempCo=C0G/NP0, Tolerance_%=5%, Value1=Unknown, Value2=50V, ValueDisplayed=10pF
C22: library part CMP-0006325-2, "CAP, CERM, 0.1 uF, 50 V, +/- 10%, X7R, AEC-Q200 Grade 1, 0402", Cap_Case=0402, Manufacturer=TDK, Supplier Part Number 1=445-6899-1-ND, TempCo=X7R, Tolerance_%=10%, Value1="0.039064 ohm", Value2=50V, ValueDisplayed=0.1uF
C23 C24 C25 C26 C27 C28: library part CMP-0036912-1, "Cap Ceramic 22uF 25V X7R 20% Pad SMD 1210 +125°C Automotive T/R", Manufacturer=TDK, Operating Temperature Range="-55°C to +125°C", TempCo=15%, Temperature Characteristic=X7R, Tolerance_%=0.2%, ValueDisplayed=22uF
C29 C30: library part CMP-0036912-1, "Cap Ceramic 22uF 25V X7R 20% Pad SMD 1210 +125°C Automotive T/R", Manufacturer=TDK, Operating Temperature Range="-55°C to +125°C", Part Number=CGA6P3X7R1E226M250AB, TempCo=15%, Temperature Characteristic=X7R, Tolerance_%=0.2%, ValueDisplayed=22uF
C31: library part CMP-0012165-3, "CAP, Aluminum Polymer, 82 uF, 16 V, +/- 20%, 0.03 ohm, D6.3xL5.8mm SMD", Cap_Case=6.3x5.8mm, Manufacturer="Wurth Elektronik", PartNumber=875105344009, Supplier Part Number 1=732-6424-1-ND, Tolerance_%=20%, Value1="0.03 ohm", Value2=16V, ValueDisplayed=82uF
C34: library part CMP-0007137-5, "CAP, CERM, 1 uF, 16 V, +/- 20%, X7R, AEC-Q200 Grade 1, 0603", Cap_Case=0603, Manufacturer=MuRata, TempCo=X7R, Tolerance_%=20%, Value1=Unknown, Value2=16V, ValueDisplayed=1uF
D1: library part CMP-0124232-1, "Diode Schottky 20 V 1A Surface Mount SOD-123FL", Digikey Part Number=NRVB120VLSFT1GOSCT-ND, Forward Current=1A, Manufacturer="On Semi", Max Surge Forward Current=45A, Mouser Part Number=863-NRVB120VLSFT1G, Operating Temperature Range="-65°C to +125°C", Peak Reverse Current=0.6mA
FID1 FID2 FID3 FID4 FID5 FID6: library part CMP-0077181-1, "Fiducial mark.  There is nothing to buy or mount.", Manufacturer=N/A
H1 H2 H3 H4: library part CMP-0003617-1, "Machine Screw, Round, #4-40 x 1/4, Nylon, Philips panhead", Manufacturer="B&F Fastener Supply", Supplier Part Number 1=H542-ND
H5 H6 H7 H8: library part CMP-0003610-1, "Standoff, Hex, 0.5\"L #4-40 Nylon", Manufacturer=Keystone, Supplier Part Number 1=36-1902C-ND
J1 J4: library part CMP-0054828-1, "Terminal Block, 5 mm, 2x1, Tin, TH", Manufacturer="Wurth Elektronik", Supplier Part Number 1=732-2026-ND
J2: library part CMP-0054953-2, "Header, 100mil, 3x2, Tin, TH", Manufacturer="TE Connectivity", PartNumber=5-146254-3
J3: library part CMP-0054949-1, "Header, 100mil, 8x1, Tin, TH", Manufacturer="TE Connectivity", Supplier Part Number 1=A106718-ND
L1: library part CMP-0084691-1, "Coupled inductor,  ohm, AEC-Q200 Grade 1, SMD", Manufacturer=TDK
L2: library part CMP-0082255-1, "Inductor, Drum Core, Powdered Iron, 6.8 µH, 10.8 A, 0.014 ohm, AEC-Q200 Grade 0, SMD", Manufacturer=Cyntec, Value1="0.014 ohm", Value2=10.8A, ValueDisplayed=6.8µH
L3: library part CMP-0093175-1, "Shielded Power Inductors 3.3uH 20% tol, 6.5mOhm 16.6A", Manufacturer=Coilcraft, Operating Temperature Range=to, Part Number=XGL6060-332MEC, Self Resonant Frequency=24MHz, Test Frequency=1MHz, Tolerance_%=20%
LBL1: library part CMP-0003625-1, "Thermal Transfer Printable Labels, 0.650\" W x 0.200\" H - 10,000 per roll", Manufacturer=Brady, Supplier Part Number 1=97C5133
Logo1: library part CMP-0074844-1
Logo2: library part CMP-0074838-1, "Texas Instrument Corporate Signature"
Logo3: library part CMP-0074847-1, "FCC_disclaimer"
Logo4: library part CMP-0074769-1
LOGO5: library part CMP-0074837-1, "IEC 61010-1 Hot Surface Warning"
NT1: library part CMP-0078142-4, "Single point connection between nets.", Manufacturer=N/A
R1: library part CMP-0022717-1, "RES, 0.51, 1%, 0.1 W, AEC-Q200 Grade 1, 0603", Manufacturer=Panasonic, Power_W=100mW, Supplier Part Number 1=P.51AJCT-ND, TempCo="300 ppm/C", Tolerance_%=1%, Value2=0.1W, Value_Code=R510, ValueDisplayed=0.51
R2 R3 R7: library part CMP-0089139-1, "49.9 kOhms ±1% 0.1W, 1/10W Chip Resistor 0603 (1608 Metric) Automotive AEC-Q200 Thick Film", Approved Alternate Part Number=541-1.00HHCT-ND, Digikey Part Number=541-49.9KHCT-ND, Manufacturer=Vishay, Mouser Part Number=71-CRCW0603-49.9K-E3, Operating Temperature Range="-55°C to +155°C", Power=100mW, TempCo=100ppm/K, Tolerance_%=1%, Voltage=75V
R4: library part CMP-0022410-4, "RES, 40.2 k, 1%, 0.1 W, AEC-Q200 Grade 0, 0603", Manufacturer=Vishay-Dale, Power_W=100mW, Supplier Part Number 1=541-40.2KHCT-ND, TempCo="100 ppm/C", Tolerance_%=1%, Value2=0.1W, Value_Code=40k2, ValueDisplayed=40.2k
R5: library part CMP-0022043-4, "RES, 13.3 k, 1%, 0.1 W, AEC-Q200 Grade 0, 0603", Manufacturer=Vishay-Dale, Power_W=100mW, Supplier Part Number 1=541-13.3KHCT-ND, TempCo="100 ppm/C", Tolerance_%=1%, Value2=0.1W, Value_Code=13k3, ValueDisplayed=13.3k
R6: library part CMP-0022218-4, "RES, 226 k, 1%, 0.1 W, AEC-Q200 Grade 0, 0603", Manufacturer=Vishay-Dale, Power_W=100mW, Supplier Part Number 1=541-226KHCT-ND, TempCo="100 ppm/C", Tolerance_%=1%, Value2=0.1W, Value_Code=226k
R8: library part CMP-0021990-4, "RES, 100 k, 1%, 0.1 W, AEC-Q200 Grade 0, 0603", Manufacturer=Vishay-Dale, Power_W=100mW, Supplier Part Number 1=541-100KHCT-ND, TempCo="100 ppm/C", Tolerance_%=1%, Value2=0.1W, Value_Code=100k
R9: library part CMP-0022448-4, "RES, 49.9, 1%, 0.1 W, AEC-Q200 Grade 0, 0603", Manufacturer=Vishay-Dale, Power_W=100mW, Supplier Part Number 1=541-49.9HCT-ND, TempCo="100 ppm/C", Tolerance_%=1%, Value2=0.1W, Value_Code=49R9, ValueDisplayed=49.9
R10: library part CMP-0021998-4, "RES, 10.0 k, 1%, 0.1 W, AEC-Q200 Grade 0, 0603", Manufacturer=Vishay-Dale, Power_W=100mW, Supplier Part Number 1=541-10.0KHCT-ND, TempCo="100 ppm/C", Tolerance_%=1%, Value2=0.1W, Value_Code=10k0, ValueDisplayed=10.0k
R11: library part CMP-0023343-3, "RES, 0, 1%, 0.1 W, AEC-Q200 Grade 0, 0603", Manufacturer="Stackpole Electronics Inc", Power_W=100mW, Supplier Part Number 1=RMCF0603ZT0R00CT-ND, TempCo=ppm/C, Tolerance_%=1%, Value2=0.1W, Value_Code=0
R12: library part CMP-0022330-4, "RES, 31.6 k, 1%, 0.1 W, AEC-Q200 Grade 0, 0603", Manufacturer=Vishay-Dale, Power_W=100mW, Supplier Part Number 1=541-31.6KHCT-ND, TempCo="100 ppm/C", Tolerance_%=1%, Value2=0.1W, Value_Code=31k6, ValueDisplayed=31.6k
R13: library part CMP-0022212-4, "RES, 21.0 k, 1%, 0.1 W, AEC-Q200 Grade 0, 0603", Manufacturer=Vishay-Dale, Power_W=100mW, Supplier Part Number 1=541-21.0KHCT-ND, TempCo="100 ppm/C", Tolerance_%=1%, Value2=0.1W, Value_Code=21k0, ValueDisplayed=21.0k
R14: library part CMP-0022628-4, "RES, 86.6 k, 1%, 0.1 W, AEC-Q200 Grade 0, 0603", Manufacturer=Vishay-Dale, Power_W=100mW, Supplier Part Number 1=541-86.6KHCT-ND, TempCo="100 ppm/C", Tolerance_%=1%, Value2=0.1W, Value_Code=86k6, ValueDisplayed=86.6k
SH-J1 SH-J2 SH-J3: library part CMP-0003623-3, "Shunt, 100mil, Gold plated, Black", Alternate Manufacturer=3M, Alternate PartNumber=969102-0000-DA, Manufacturer=Samtec, Supplier Part Number 1=SAM8858-ND
TP1 TP2 TP3 TP4 TP5 TP6 TP7: library part CMP-0055162-1, "Test Point, Miniature, SMT", Manufacturer=Keystone, PartNumber=5019, Supplier Part Number 1=36-5019TR-ND
U1: library part CMP-0127710-1, "65V, 8A Buck Converters Optimized for Inverting or Non-Inverting Outputs", Manufacturer="Texas Instruments", Max Supply Voltage=65V, Min Supply Voltage=3V, Negative Voltage Available=true, Nominal Supply Current=42-56uA, Operating Temperature Range="-40°C to +150°C", Output Voltage=0.8-60V, Switching Frequency=300-2200kHz
VIN_S: library part CMP-0055152-1, "Test Point, Miniature, SMT", Manufacturer=Keystone, Supplier Part Number 1=36-5015TR-ND
ZZ1: library part CMP-0077236-1
ZZ2: library part CMP-0077237-1
ZZ3: library part CMP-0077238-1
ZZ4: library part CMP-0077238-1, "These assemblies must comply with workmanship standards IPC-A-610 Class 2, unless otherwise specified."
ZZ5: library part CMP-0077238-1, "Install Shunt Jumper SH-J1 onto J3 pins 2-3 BIAS-VOUT)"
ZZ6: library part CMP-0077238-1, "Install Shunt Jumper SH-J2 onto J3 pins 11-12 (EN-VIN)"
ZZ7: library part CMP-0077238-1, "Install Shunt Jumper SH-J4 onto J3 pin 8 (SYNC))"
ZZ8: library part CMP-0003616-3

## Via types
v1: diameter 20, hole 8, Top Layer to Bottom Layer, tented both sides, 441 vias
v2: diameter 19.68, hole 7.87, Top Layer to Bottom Layer, tented both sides, 208 vias
v3: diameter 20, hole 8, Top Layer to Bottom Layer, 28 vias

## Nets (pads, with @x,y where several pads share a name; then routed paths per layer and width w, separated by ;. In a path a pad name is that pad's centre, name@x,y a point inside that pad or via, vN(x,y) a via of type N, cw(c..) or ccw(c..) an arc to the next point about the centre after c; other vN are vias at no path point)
-VOUT: C12.2 C13.2 C14.2 C15.2 C16.2 C17.2 C18.2 C20.2 C21.1 C23.1 C24.1 C25.1 C26.1 C27.1 C28.1 C29.1 C30.1 C31.2 C32.2 C35.2 D1.2 J4.1 R2.1 R3.1 R4.1 R10.1 TP4.1 U1.8 U1.12 U1.13 U1.22 U1.23 U1.27 | length 22.9
  Top Layer w10: U1.8@2286.93,1428.07 2281.4,1428.07 2291,1418.47 2290.77,1418.24 U1.8@2294.22,1418.24
  other v1: 2901,85 3001,85 3103,85 3205,85 3305,85 3405,85 3506,85 3615,85 3915,85 3456,183 2951,184 3053,184 3163,184 3255,184 3355,184 3507,274 2902,275 3002,275 3104,275 3206,275 3306,275 3406,275 3559,362 3456,363 2951,364 3053,364 3163,364 3255,364 3355,364 3915,414 3158,446 3250,446 3105,551 3204,551 3305,551 3608,551 3709,551 3810,551 2902,552 3002,552 3407,552 3507,552 3658,648 3759,648 3860,648 2902,649 3053,649 3153,649 3255,649 3357,649 3457,649 3557,649 1646,666 1747,666 1866,666 1966,666 2067,666 2168,666 2268,666 2417,666 2517,666 2618,666 2718,666 3608,747 3709,747 3810,747 2909,748 3003,748 3103,748 3205,748 3315,748 3407,748 3507,748 1596,757 1696,757 1916,757 2016,757 2467,767 2567,767 2667,767 1647,848 1747,848 1866,848 1967,848 2067,848 2417,848 2518,848 2618,848 2718,848 3557,849 3659,849 3760,849 3861,849 2852,850 2952,850 3052,850 3154,850 3256,850 3356,850 3456,850 2227,908 2305,908 1597,947 1697,947 1917,947 2017,947 2167,947 2468,947 2568,947 2668,947 3507,948 3609,948 3710,948 3811,948 2902,949 3002,949 3104,949 3214,949 3306,949 3406,949 2266,954 2227,995 2301,995 1648,1038 1748,1038 1867,1038 1968,1038 2068,1038 2167,1038 2418,1038 2519,1038 2619,1038 2719,1038 3558,1039 3660,1039 3761,1039 3862,1039 2853,1040 2953,1040 3053,1040 3155,1040 3257,1040 3357,1040 3457,1040 2167,1125 1597,1133 1697,1133 1917,1133 2017,1133 2306,1133 2337,1133 2373,1133 2468,1133 2568,1133 2668,1133 3507,1134 3609,1134 3710,1134 3811,1134 2902,1135 3002,1135 3104,1135 3214,1135 3306,1135 3406,1135 2306,1171 2337,1171 2373,1171 2091,1189 2156,1190 2262,1191.69 1740,1195 2124,1208 2373,1214 2091,1216 2418,1229 2519,1229 2619,1229 2719,1229 3558,1230 3660,1230 2853,1231 2953,1231 3053,1231 3155,1231 3257,1231 3357,1231 3457,1231 3795,1239 3723,1240 3869,1240 2319,1253 1690,1258 1790,1258 1917,1258 2017,1258 2418,1277 3747,1279 3795,1279 3842,1279 3723,1315 3795,1315 3869,1316 2468,1324 2568,1324 1740,1351 1840,1351 3515,1356 3617,1356 2810,1357 2910,1357 3010,1357 3112,1357 3214,1357 3314,1357 3414,1357 2124,1367 1926,1368 2454,1378 2323,1386 3669,1400 3798,1400 3879,1400 2318,1412 1690,1440 1791,1440 1937,1465 1967,1465 1997,1465 2027,1465 2399,1466 2429,1466 2459,1466 2489,1466 2558,1466 2659,1466 2961,1466 3365,1466 3567,1466 3669,1466 3879,1466 2759,1467 2860,1467 3062,1467 3163,1467 3264,1467 3466,1467 1937,1486 1967,1486 1997,1486 2027,1486 2399,1487 2429,1487 2459,1487 2489,1487 2059,1494 2080,1494 2357,1496 2378,1496 2175,1539 2201,1539 2227,1539 2253,1539 3011,1548 2608,1549 2709,1549 2810,1549 2910,1549 3112,1549 2961,1644 2564,1645 2659,1645 2759,1645 2860,1645 3062,1645 2608,1736 2709,1736 2810,1736 2910,1736 1690,1831 1790,1831 1891,1831 1991,1831 2457,1831 2557,1831 2658,1831 2758,1831 2859,1831 1740,1922 1840,1922 1941,1922 2507,1922 2607,1922 2708,1922 2809,1922 2909,1922 1690,2010 1790,2011 1891,2013 1991,2013 2457,2013 2558,2013 2658,2013 2758,2013 2859,2013
  other v2: 2174.63,1460.57 2201.01,1460.57 2226.99,1460.57 2253.37,1460.57 2174.63,1480.25 2201.01,1480.25 2226.99,1480.25 2253.37,1480.25 2174.63,1499.94 2201.01,1499.94 2226.99,1499.94 2253.37,1499.94 2174.63,1519.62 2201.01,1519.62 2226.99,1519.62 2253.37,1519.62
BST: C22.1 U1.19 | length 37
  Top Layer w10: U1.19@2184,1589 C22.1@2184,1626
